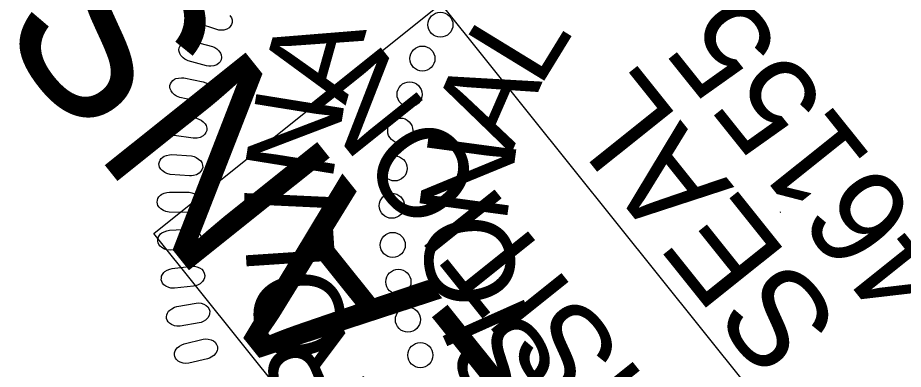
# Model space of a CAD drawing. Extents: x 473437 to 475344, y 504319 to 506318.
# Drawn here: x 473528.3 to 473584.9, y 505648.7 to 505671.2 of the extents above; entities that cross this region are included whole.
import ezdxf

# ---------------------------------------------------------------- set-up
doc = ezdxf.new("R2010")
doc.units = 0
doc.layers.add('Sheet PE Seal Cell', color=7, linetype='Continuous')
doc.layers.add('Sheet Sticker Incomplete CELL', color=7, linetype='Continuous')

msp = doc.modelspace()

# ---------------------------------------------------------------- linework, layer by layer
at = {"layer": 'Sheet PE Seal Cell'}
msp.add_line((473577.05, 505658.756), (473577.087, 505658.785), dxfattribs=at)
msp.add_lwpolyline([(473541.878, 505671.334), (473541.974, 505671.183), (473542.018, 505671.065), (473542.024, 505670.897), (473541.993, 505670.749), (473541.908, 505670.621), (473541.826, 505670.538), (473541.69, 505670.45), (473541.492, 505670.392), (473541.3, 505670.387), (473541.167, 505670.401), (473541.04, 505670.429), (473539.88, 505670.827), (473539.684, 505670.934), (473539.569, 505671.028), (473539.445, 505671.189), (473539.373, 505671.317)], dxfattribs=at)
for points in [[(473540.396, 505668.119), (473539.213, 505668.444), (473539.012, 505668.538), (473538.891, 505668.625), (473538.756, 505668.779), (473538.677, 505668.901), (473538.63, 505669.03), (473538.619, 505669.142), (473538.629, 505669.256), (473538.678, 505669.359), (473538.739, 505669.465), (473538.824, 505669.551), (473538.948, 505669.625), (473539.041, 505669.662), (473539.203, 505669.687), (473539.392, 505669.697), (473539.551, 505669.677), (473540.765, 505669.351), (473540.922, 505669.285), (473541.046, 505669.204), (473541.175, 505669.076), (473541.281, 505668.93), (473541.332, 505668.816), (473541.348, 505668.649), (473541.328, 505668.499), (473541.25, 505668.366), (473541.174, 505668.278), (473541.044, 505668.181), (473540.849, 505668.111), (473540.658, 505668.094), (473540.525, 505668.099)], [(473539.886, 505665.84), (473538.685, 505666.09), (473538.477, 505666.172), (473538.351, 505666.251), (473538.208, 505666.395), (473538.12, 505666.513), (473538.065, 505666.639), (473538.048, 505666.749), (473538.05, 505666.864), (473538.093, 505666.969), (473538.147, 505667.08), (473538.227, 505667.171), (473538.346, 505667.253), (473538.436, 505667.295), (473538.597, 505667.33), (473538.784, 505667.352), (473538.945, 505667.342), (473540.177, 505667.093), (473540.338, 505667.037), (473540.466, 505666.964), (473540.603, 505666.844), (473540.718, 505666.706), (473540.776, 505666.594), (473540.803, 505666.428), (473540.791, 505666.278), (473540.722, 505666.14), (473540.652, 505666.048), (473540.529, 505665.943), (473540.338, 505665.861), (473540.148, 505665.832), (473540.016, 505665.829)], [(473539.529, 505663.491), (473538.315, 505663.665), (473538.104, 505663.733), (473537.972, 505663.804), (473537.821, 505663.939), (473537.726, 505664.051), (473537.663, 505664.173), (473537.638, 505664.282), (473537.634, 505664.396), (473537.67, 505664.505), (473537.716, 505664.619), (473537.79, 505664.714), (473537.904, 505664.803), (473537.992, 505664.851), (473538.149, 505664.896), (473538.335, 505664.93), (473538.496, 505664.93), (473539.741, 505664.759), (473539.906, 505664.713), (473540.038, 505664.649), (473540.183, 505664.537), (473540.305, 505664.406), (473540.371, 505664.299), (473540.408, 505664.135), (473540.406, 505663.984), (473540.346, 505663.842), (473540.281, 505663.745), (473540.165, 505663.634), (473539.98, 505663.539), (473539.792, 505663.498), (473539.66, 505663.487)], [(473539.298, 505661.071), (473538.074, 505661.168), (473537.859, 505661.222), (473537.723, 505661.286), (473537.563, 505661.411), (473537.462, 505661.516), (473537.391, 505661.634), (473537.359, 505661.742), (473537.349, 505661.856), (473537.377, 505661.965), (473537.417, 505662.082), (473537.484, 505662.182), (473537.592, 505662.278), (473537.677, 505662.332), (473537.831, 505662.387), (473538.015, 505662.432), (473538.175, 505662.442), (473539.429, 505662.35), (473539.596, 505662.314), (473539.731, 505662.258), (473539.883, 505662.156), (473540.014, 505662.034), (473540.086, 505661.93), (473540.133, 505661.769), (473540.141, 505661.618), (473540.089, 505661.473), (473540.031, 505661.372), (473539.922, 505661.253), (473539.743, 505661.147), (473539.559, 505661.095), (473539.428, 505661.076)], [(473539.222, 505658.741), (473537.996, 505658.762), (473537.777, 505658.802), (473537.638, 505658.857), (473537.47, 505658.972), (473537.362, 505659.071), (473537.285, 505659.184), (473537.246, 505659.289), (473537.229, 505659.403), (473537.25, 505659.514), (473537.282, 505659.633), (473537.343, 505659.737), (473537.445, 505659.84), (473537.526, 505659.898), (473537.677, 505659.962), (473537.857, 505660.02), (473538.017, 505660.04), (473539.273, 505660.026), (473539.443, 505660.001), (473539.582, 505659.954), (473539.739, 505659.862), (473539.878, 505659.747), (473539.956, 505659.649), (473540.013, 505659.491), (473540.03, 505659.341), (473539.988, 505659.192), (473539.936, 505659.088), (473539.834, 505658.963), (473539.663, 505658.847), (473539.482, 505658.782), (473539.352, 505658.754)], [(473539.3, 505656.377), (473538.075, 505656.32), (473537.854, 505656.347), (473537.712, 505656.393), (473537.537, 505656.497), (473537.423, 505656.589), (473537.338, 505656.697), (473537.294, 505656.801), (473537.268, 505656.912), (473537.283, 505657.025), (473537.308, 505657.145), (473537.363, 505657.252), (473537.457, 505657.362), (473537.534, 505657.426), (473537.681, 505657.5), (473537.857, 505657.568), (473538.016, 505657.597), (473539.271, 505657.663), (473539.441, 505657.648), (473539.583, 505657.61), (473539.746, 505657.528), (473539.891, 505657.422), (473539.975, 505657.329), (473540.042, 505657.175), (473540.069, 505657.026), (473540.036, 505656.875), (473539.991, 505656.768), (473539.897, 505656.637), (473539.733, 505656.51), (473539.557, 505656.434), (473539.429, 505656.398)], [(473539.556, 505654.02), (473538.337, 505653.887), (473538.114, 505653.9), (473537.97, 505653.937), (473537.789, 505654.03), (473537.669, 505654.114), (473537.578, 505654.217), (473537.527, 505654.317), (473537.495, 505654.427), (473537.502, 505654.54), (473537.52, 505654.662), (473537.567, 505654.773), (473537.655, 505654.887), (473537.728, 505654.955), (473537.869, 505655.039), (473538.041, 505655.118), (473538.197, 505655.157), (473539.446, 505655.302), (473539.617, 505655.297), (473539.76, 505655.268), (473539.929, 505655.197), (473540.079, 505655.101), (473540.17, 505655.013), (473540.247, 505654.863), (473540.282, 505654.716), (473540.259, 505654.564), (473540.22, 505654.454), (473540.136, 505654.316), (473539.98, 505654.18), (473539.809, 505654.093), (473539.683, 505654.05)], [(473539.916, 505651.673), (473538.708, 505651.463), (473538.486, 505651.463), (473538.339, 505651.49), (473538.153, 505651.572), (473538.028, 505651.648), (473537.93, 505651.746), (473537.873, 505651.842), (473537.834, 505651.949), (473537.835, 505652.063), (473537.844, 505652.186), (473537.885, 505652.299), (473537.965, 505652.419), (473538.034, 505652.492), (473538.169, 505652.584), (473538.336, 505652.673), (473538.489, 505652.723), (473539.726, 505652.945), (473539.897, 505652.952), (473540.042, 505652.932), (473540.215, 505652.871), (473540.372, 505652.784), (473540.467, 505652.702), (473540.553, 505652.557), (473540.598, 505652.414), (473540.585, 505652.259), (473540.553, 505652.148), (473540.476, 505652.005), (473540.33, 505651.859), (473540.165, 505651.762), (473540.042, 505651.71)], [(473540.451, 505649.38), (473539.258, 505649.095), (473539.036, 505649.08), (473538.888, 505649.099), (473538.697, 505649.168), (473538.568, 505649.237), (473538.464, 505649.328), (473538.401, 505649.42), (473538.355, 505649.525), (473538.349, 505649.638), (473538.35, 505649.762), (473538.384, 505649.877), (473538.457, 505650.002), (473538.52, 505650.079), (473538.651, 505650.18), (473538.811, 505650.279), (473538.961, 505650.339), (473540.181, 505650.638), (473540.351, 505650.656), (473540.498, 505650.644), (473540.674, 505650.594), (473540.836, 505650.518), (473540.936, 505650.442), (473541.031, 505650.303), (473541.085, 505650.162), (473541.081, 505650.008), (473541.057, 505649.894), (473540.989, 505649.747), (473540.852, 505649.592), (473540.693, 505649.484), (473540.574, 505649.426)]]:
    msp.add_lwpolyline(points, close=True, dxfattribs=at)
for centre in [(473555.332, 505670.744), (473554.183, 505668.58), (473553.361, 505666.291), (473552.763, 505663.977), (473552.408, 505661.552), (473552.226, 505659.164), (473552.288, 505656.663), (473552.647, 505654.3), (473553.256, 505651.881), (473554.051, 505649.611)]:
    msp.add_circle(centre, 0.801, dxfattribs=at)
at = {"layer": 'Sheet Sticker Incomplete CELL'}
msp.add_lwpolyline([(473647.22, 505557.313), (473628.873, 505542.629), (473537.02, 505657.398), (473555.367, 505672.082)], close=True, dxfattribs=at)

# ---------------------------------------------------------------- texts
at = {"layer": 'Sheet PE Seal Cell'}
for s, height, rotation, p in [('46155', 6.2363, 128.6526, (473588.84, 505654.883)), ('L', 5.669, 58.5021, (473561.643, 505666.635)), ('A', 5.669, 74.344, (473549.269, 505665.559)), ('SEAL', 6.2363, 128.6526, (473581.066, 505651.669)), ('A', 5.669, 66.4419, (473559.851, 505662.481)), ('N', 5.669, 80.8334, (473548.392, 505660.605)), ('N', 5.669, 82.3215, (473559.531, 505657.951)), ('I', 5.669, 87.3228, (473548.411, 505658.309)), ('L', 5.669, 93.8121, (473548.647, 505655.048)), ('O', 5.669, 98.2011, (473560.426, 505653.145)), ('O', 5.669, 100.3015, (473549.628, 505649.771)), ('I', 5.669, 114.0807, (473561.232, 505651.863)), ('S', 5.669, 122.0205, (473563.113, 505648.502)), ('R', 5.669, 113.2802, (473550.964, 505647.055))]:
    msp.add_text(s, height=height, rotation=rotation, dxfattribs=at).set_placement(p)
at = {"layer": 'Sheet Sticker Incomplete CELL'}
for s, height, p in [('INCOMPLETE PLANS', 11.52, (473632.493, 505556.99)), ('DO NOT USE FOR R/W ACQUISITION', 5.76, (473635.889, 505563.87))]:
    msp.add_text(s, height=height, rotation=128.6712, dxfattribs=at).set_placement(p)

doc.saveas('drawing.dxf')
